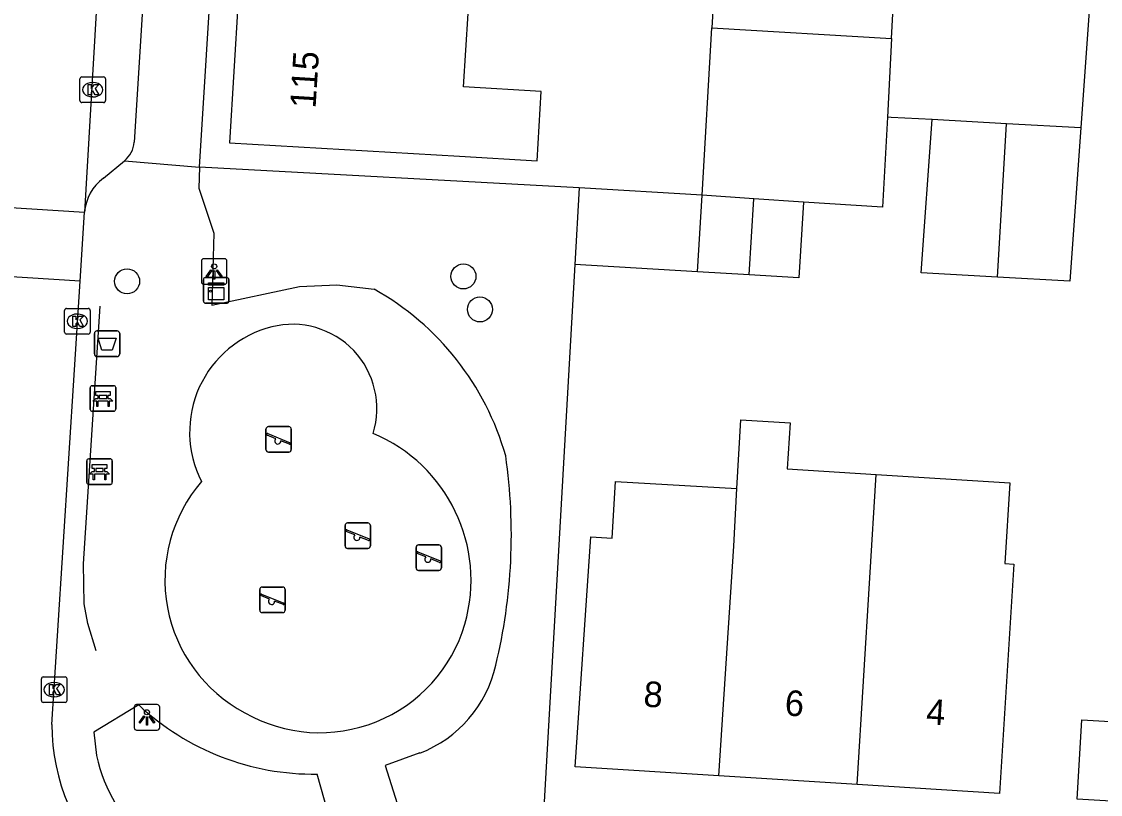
# Model space of a CAD drawing. Extents: x 160107 to 160928, y 382056 to 382918.
# Drawn here: x 160559.79 to 160601.98, y 382517.33 to 382547.57 of the extents above; entities that cross this region are included whole.
import ezdxf

# ---------------------------------------------------------------- set-up
doc = ezdxf.new("R2010")
doc.units = 0
for name, color, linetype in [('IMGEO_Afvalbak', 7, 'Continuous'), ('IMGEO_Bank', 7, 'Continuous'), ('IMGEO_Boom', 7, 'Continuous'), ('IMGEO_Groenvoorziening', 7, 'Continuous'), ('IMGEO_Hek', 7, 'Continuous'), ('IMGEO_Kast', 7, 'Continuous'), ('IMGEO_Kolk', 7, 'Continuous'), ('IMGEO_Lichtpunt', 7, 'Continuous'), ('IMGEO_Pand', 7, 'Continuous'), ('IMGEO_Pand_nummerreeks', 7, 'Continuous'), ('IMGEO_Rijbaan_lokaal_open', 7, 'Continuous'), ('IMGEO_Speelvoorziening', 7, 'Continuous'), ('IMGEO_Voetpad_open', 7, 'Continuous')]:
    doc.layers.add(name, color=color, linetype=linetype)

msp = doc.modelspace()

# ---------------------------------------------------------------- linework, layer by layer
at = {"layer": 'IMGEO_Afvalbak'}
for p, q in [((160562.74, 382535.464), (160563.53, 382535.464)), ((160563.53, 382535.464), (160562.74, 382535.464)), ((160562.64, 382534.564), (160562.64, 382535.364)), ((160562.64, 382535.364), (160562.64, 382534.564)), ((160563.63, 382535.364), (160563.63, 382534.564)), ((160563.63, 382534.564), (160563.63, 382535.364)), ((160563.53, 382534.464), (160562.74, 382534.464)), ((160562.74, 382534.464), (160563.53, 382534.464))]:
    msp.add_line(p, q, dxfattribs=at)
msp.add_lwpolyline([(160562.783, 382535.178), (160563.487, 382535.178), (160563.338, 382534.708), (160562.932, 382534.708), (160562.783, 382535.178)], dxfattribs=at)
for centre, start, end in [((160562.74, 382535.364), 90, 180), ((160562.74, 382535.364), 90, 180), ((160563.53, 382535.364), 0, 90), ((160563.53, 382535.364), 360, 90), ((160562.74, 382534.564), 180, 270), ((160562.74, 382534.564), 180, 270), ((160563.53, 382534.564), 270, 0), ((160563.53, 382534.564), 270, 0)]:
    msp.add_arc(centre, 0.1, start, end, dxfattribs=at)
at = {"layer": 'IMGEO_Bank'}
for p, q in [((160562.476, 382532.397), (160562.476, 382533.238)), ((160562.476, 382533.238), (160562.476, 382532.397)), ((160562.551, 382533.322), (160563.392, 382533.322)), ((160563.392, 382533.322), (160562.551, 382533.322)), ((160562.785, 382532.828), (160562.785, 382532.934)), ((160562.829, 382532.934), (160562.829, 382532.828)), ((160563.117, 382532.94), (160562.835, 382532.94)), ((160563.123, 382532.828), (160563.123, 382532.934)), ((160563.167, 382532.934), (160563.167, 382532.828)), ((160563.476, 382533.247), (160563.476, 382532.406)), ((160563.476, 382532.406), (160563.476, 382533.247)), ((160563.173, 382532.72), (160562.78, 382532.72)), ((160562.835, 382532.822), (160563.117, 382532.822)), ((160563.401, 382532.322), (160562.56, 382532.322)), ((160562.56, 382532.322), (160563.401, 382532.322)), ((160562.417, 382530.462), (160563.258, 382530.462)), ((160563.258, 382530.462), (160562.417, 382530.462)), ((160562.342, 382529.537), (160562.342, 382530.378)), ((160562.342, 382530.378), (160562.342, 382529.537)), ((160562.651, 382529.968), (160562.651, 382530.074)), ((160562.695, 382530.074), (160562.695, 382529.968)), ((160562.983, 382530.08), (160562.701, 382530.08)), ((160562.989, 382529.968), (160562.989, 382530.074)), ((160563.033, 382530.074), (160563.033, 382529.968)), ((160563.342, 382530.387), (160563.342, 382529.546)), ((160563.342, 382529.546), (160563.342, 382530.387)), ((160563.039, 382529.86), (160562.646, 382529.86)), ((160562.701, 382529.962), (160562.983, 382529.962)), ((160563.267, 382529.462), (160562.426, 382529.462)), ((160562.426, 382529.462), (160563.267, 382529.462))]:
    msp.add_line(p, q, dxfattribs=at)
for points in [[(160562.779, 382532.94), (160562.693, 382532.94), (160562.693, 382533.101), (160563.256, 382533.101), (160563.256, 382532.94), (160563.173, 382532.94)], [(160562.723, 382532.72), (160562.581, 382532.72), (160562.693, 382532.822), (160562.779, 382532.822)], [(160562.773, 382532.713), (160562.773, 382532.506), (160562.73, 382532.506), (160562.73, 382532.713)], [(160563.173, 382532.822), (160563.256, 382532.822), (160563.368, 382532.72), (160563.229, 382532.72)], [(160563.223, 382532.713), (160563.223, 382532.506), (160563.179, 382532.506), (160563.179, 382532.713)], [(160562.645, 382530.08), (160562.559, 382530.08), (160562.559, 382530.241), (160563.122, 382530.241), (160563.122, 382530.08), (160563.039, 382530.08)], [(160562.589, 382529.86), (160562.447, 382529.86), (160562.559, 382529.962), (160562.645, 382529.962)], [(160562.639, 382529.853), (160562.639, 382529.646), (160562.596, 382529.646), (160562.596, 382529.853)], [(160563.039, 382529.962), (160563.122, 382529.962), (160563.234, 382529.86), (160563.095, 382529.86)], [(160563.089, 382529.853), (160563.089, 382529.646), (160563.045, 382529.646), (160563.045, 382529.853)]]:
    msp.add_lwpolyline(points, dxfattribs=at)
for centre, radius, start, end in [((160562.554, 382533.244), 0.0779, 92.4484, 184.2845), ((160562.554, 382533.244), 0.0779, 92.4484, 184.2845), ((160562.778, 382532.933), 0.00671, 2.8957, 87.1043), ((160562.835, 382532.933), 0.00671, 92.8957, 177.1043), ((160563.117, 382532.933), 0.00671, 2.8957, 87.1043), ((160563.174, 382532.933), 0.00671, 92.8957, 177.1043), ((160563.398, 382533.244), 0.0779, 2.4484, 94.2845), ((160563.398, 382533.244), 0.0779, 2.4484, 94.2845), ((160562.723, 382532.713), 0.00671, 2.8957, 87.1043), ((160562.78, 382532.713), 0.00671, 92.8957, 177.1043), ((160562.778, 382532.829), 0.00671, 272.8957, 357.1043), ((160562.835, 382532.829), 0.00671, 182.8957, 267.1043), ((160563.117, 382532.829), 0.00671, 272.8957, 357.1043), ((160563.174, 382532.829), 0.00671, 182.8957, 267.1043), ((160563.172, 382532.713), 0.00671, 2.8957, 87.1043), ((160563.229, 382532.713), 0.00671, 92.8957, 177.1043), ((160562.554, 382532.4), 0.0779, 182.4484, 274.2845), ((160562.554, 382532.4), 0.0779, 182.4484, 274.2845), ((160563.398, 382532.4), 0.0779, 272.4484, 4.2845), ((160563.398, 382532.4), 0.0779, 272.4484, 4.2845), ((160562.42, 382530.384), 0.0779, 92.4484, 184.2845), ((160562.42, 382530.384), 0.0779, 92.4484, 184.2845), ((160563.264, 382530.384), 0.0779, 2.4484, 94.2845), ((160563.264, 382530.384), 0.0779, 2.4484, 94.2845), ((160562.644, 382530.073), 0.00671, 2.8957, 87.1043), ((160562.644, 382529.969), 0.00671, 272.8957, 357.1043), ((160562.701, 382530.073), 0.00671, 92.8957, 177.1043), ((160562.701, 382529.969), 0.00671, 182.8957, 267.1043), ((160562.983, 382530.073), 0.00671, 2.8957, 87.1043), ((160562.983, 382529.969), 0.00671, 272.8957, 357.1043), ((160563.04, 382530.073), 0.00671, 92.8957, 177.1043), ((160563.04, 382529.969), 0.00671, 182.8957, 267.1043), ((160562.589, 382529.853), 0.00671, 2.8957, 87.1043), ((160562.646, 382529.853), 0.00671, 92.8957, 177.1043), ((160563.038, 382529.853), 0.00671, 2.8957, 87.1043), ((160563.095, 382529.853), 0.00671, 92.8957, 177.1043), ((160563.264, 382529.54), 0.0779, 272.4484, 4.2845), ((160563.264, 382529.54), 0.0779, 272.4484, 4.2845), ((160562.42, 382529.54), 0.0779, 182.4484, 274.2845), ((160562.42, 382529.54), 0.0779, 182.4484, 274.2845)]:
    msp.add_arc(centre, radius, start, end, dxfattribs=at)
at = {"layer": 'IMGEO_Boom'}
for centre in [(160577.073, 382537.598), (160563.92, 382537.407), (160577.718, 382536.307)]:
    msp.add_circle(centre, 0.489, dxfattribs=at)
at = {"layer": 'IMGEO_Groenvoorziening'}
for points in [[(160581.6, 382541.063), (160566.75, 382541.876)], [(160581.423, 382538.059), (160580.178, 382516.126)]]:
    msp.add_lwpolyline(points, dxfattribs=at)
at = {"layer": 'IMGEO_Hek'}
msp.add_lwpolyline([(160562.715, 382522.952), (160562.379, 382524.021), (160562.241, 382524.794), (160562.21, 382526.361), (160562.864, 382536.433)], dxfattribs=at)
at = {"layer": 'IMGEO_Kast'}
for p, q in [((160566.902, 382536.629), (160566.902, 382537.47)), ((160566.902, 382537.47), (160566.902, 382536.629)), ((160566.977, 382537.554), (160567.818, 382537.554)), ((160567.818, 382537.554), (160566.977, 382537.554)), ((160567.902, 382537.479), (160567.902, 382536.638)), ((160567.902, 382536.638), (160567.902, 382537.479)), ((160567.827, 382536.554), (160566.986, 382536.554)), ((160566.986, 382536.554), (160567.827, 382536.554))]:
    msp.add_line(p, q, dxfattribs=at)
for points in [[(160567.097, 382537.344), (160567.697, 382537.344), (160567.697, 382537.259), (160567.097, 382537.259), (160567.097, 382537.344)], [(160567.097, 382537.169), (160567.697, 382537.169), (160567.697, 382536.68), (160567.097, 382536.68), (160567.097, 382537.169)]]:
    msp.add_lwpolyline(points, dxfattribs=at)
msp.add_circle((160567.181, 382537.018), 0.0377, dxfattribs=at)
for centre, start, end in [((160566.98, 382537.476), 92.4484, 184.2845), ((160566.98, 382537.476), 92.4484, 184.2845), ((160567.824, 382537.476), 2.4484, 94.2845), ((160567.824, 382537.476), 2.4484, 94.2845), ((160566.98, 382536.632), 182.4484, 274.2845), ((160566.98, 382536.632), 182.4484, 274.2845), ((160567.824, 382536.632), 272.4484, 4.2845), ((160567.824, 382536.632), 272.4484, 4.2845)]:
    msp.add_arc(centre, 0.0779, start, end, dxfattribs=at)
at = {"layer": 'IMGEO_Kolk'}
for p, q in [((160562.074, 382544.475), (160562.074, 382545.327)), ((160562.149, 382545.401), (160563.001, 382545.401)), ((160562.562, 382545.181), (160562.587, 382545.181)), ((160563.075, 382545.327), (160563.075, 382544.475)), ((160563.001, 382544.401), (160562.149, 382544.401)), ((160562.585, 382544.621), (160562.56, 382544.621)), ((160561.55, 382536.346), (160562.402, 382536.346)), ((160561.475, 382535.42), (160561.475, 382536.272)), ((160561.963, 382536.126), (160561.988, 382536.126)), ((160562.476, 382536.272), (160562.476, 382535.42)), ((160561.986, 382535.566), (160561.961, 382535.566)), ((160562.402, 382535.346), (160561.55, 382535.346)), ((160560.568, 382521.007), (160560.568, 382521.859)), ((160560.643, 382521.933), (160561.495, 382521.933)), ((160561.056, 382521.713), (160561.081, 382521.713)), ((160561.569, 382521.859), (160561.569, 382521.007)), ((160561.079, 382521.153), (160561.054, 382521.153)), ((160561.495, 382520.933), (160560.643, 382520.933))]:
    msp.add_line(p, q, dxfattribs=at)
for points in [[(160562.074, 382544.475), (160562.074, 382545.327)], [(160562.149, 382545.401), (160563.001, 382545.401)], [(160563.075, 382545.327), (160563.075, 382544.475)], [(160562.395, 382545.101), (160562.518, 382545.101), (160562.518, 382544.95), (160562.648, 382545.101), (160562.812, 382545.101), (160562.666, 382544.95), (160562.819, 382544.701), (160562.667, 382544.701), (160562.582, 382544.865), (160562.518, 382544.798), (160562.518, 382544.701), (160562.395, 382544.701), (160562.395, 382545.101)], [(160563.001, 382544.401), (160562.149, 382544.401)], [(160561.55, 382536.346), (160562.402, 382536.346)], [(160561.475, 382535.42), (160561.475, 382536.272)], [(160561.796, 382536.046), (160561.919, 382536.046), (160561.919, 382535.895), (160562.049, 382536.046), (160562.213, 382536.046), (160562.067, 382535.895), (160562.22, 382535.646), (160562.068, 382535.646), (160561.983, 382535.81), (160561.919, 382535.743), (160561.919, 382535.646), (160561.796, 382535.646), (160561.796, 382536.046)], [(160562.476, 382536.272), (160562.476, 382535.42)], [(160562.402, 382535.346), (160561.55, 382535.346)], [(160560.568, 382521.007), (160560.568, 382521.859)], [(160560.643, 382521.933), (160561.495, 382521.933)], [(160560.889, 382521.633), (160561.012, 382521.633), (160561.012, 382521.482), (160561.142, 382521.633), (160561.306, 382521.633), (160561.16, 382521.482), (160561.313, 382521.233), (160561.161, 382521.233), (160561.076, 382521.397), (160561.012, 382521.33), (160561.012, 382521.233), (160560.889, 382521.233), (160560.889, 382521.633)], [(160561.569, 382521.859), (160561.569, 382521.007)], [(160561.495, 382520.933), (160560.643, 382520.933)]]:
    msp.add_lwpolyline(points, dxfattribs=at)
for centre, start, end in [((160562.151, 382545.325), 91.552, 178.448), ((160562.151, 382545.325), 91.552, 178.448), ((160562.999, 382545.325), 1.552, 88.448), ((160562.999, 382545.325), 1.552, 88.448), ((160562.151, 382544.477), 181.552, 268.448), ((160562.151, 382544.477), 181.552, 268.448), ((160562.999, 382544.477), 271.552, 358.448), ((160562.999, 382544.477), 271.552, 358.448), ((160561.552, 382536.27), 91.552, 178.448), ((160561.552, 382536.27), 91.552, 178.448), ((160562.4, 382536.27), 1.552, 88.448), ((160562.4, 382536.27), 1.552, 88.448), ((160561.552, 382535.422), 181.552, 268.448), ((160561.552, 382535.422), 181.552, 268.448), ((160562.4, 382535.422), 271.552, 358.448), ((160562.4, 382535.422), 271.552, 358.448), ((160560.645, 382521.857), 91.552, 178.448), ((160560.645, 382521.857), 91.552, 178.448), ((160561.493, 382521.857), 1.552, 88.448), ((160561.493, 382521.857), 1.552, 88.448), ((160560.645, 382521.009), 181.552, 268.448), ((160560.645, 382521.009), 181.552, 268.448), ((160561.493, 382521.009), 271.552, 358.448), ((160561.493, 382521.009), 271.552, 358.448)]:
    msp.add_arc(centre, 0.0765, start, end, dxfattribs=at)
for centre, major_axis, ratio, start_param, end_param in [((160562.561, 382544.901), (-0.387, 0.002), 0.722429, 4.712389, 7.853982), ((160562.586, 382544.901), (-0.39, 0.002), 0.717154, 1.570796, 4.712389), ((160561.962, 382535.846), (-0.387, 0.002), 0.722429, 4.712389, 7.853982), ((160561.987, 382535.846), (-0.39, 0.002), 0.717154, 1.570796, 4.712389), ((160561.055, 382521.433), (-0.387, 0.002), 0.722429, 4.712389, 7.853982), ((160561.08, 382521.433), (-0.39, 0.002), 0.717154, 1.570796, 4.712389)]:
    msp.add_ellipse(centre, major_axis=major_axis, ratio=ratio, start_param=start_param, end_param=end_param, dxfattribs=at)
at = {"layer": 'IMGEO_Lichtpunt'}
for p, q in [((160566.824, 382538.195), (160566.824, 382537.388)), ((160566.824, 382538.195), (160566.824, 382537.388)), ((160567.726, 382538.29), (160566.918, 382538.29)), ((160567.726, 382538.29), (160566.918, 382538.29)), ((160567.82, 382537.388), (160567.82, 382538.195)), ((160567.82, 382537.388), (160567.82, 382538.195)), ((160566.918, 382537.294), (160567.726, 382537.294)), ((160566.918, 382537.294), (160567.726, 382537.294)), ((160564.198, 382520.751), (160564.198, 382519.944)), ((160564.198, 382520.751), (160564.198, 382519.944)), ((160565.1, 382520.846), (160564.292, 382520.846)), ((160565.1, 382520.846), (160564.292, 382520.846)), ((160565.194, 382519.944), (160565.194, 382520.751)), ((160565.194, 382519.944), (160565.194, 382520.751)), ((160564.292, 382519.85), (160565.1, 382519.85)), ((160564.292, 382519.85), (160565.1, 382519.85))]:
    msp.add_line(p, q, dxfattribs=at)
for points in [[(160567.198, 382537.859), (160567.237, 382537.831), (160567.049, 382537.569), (160567.011, 382537.596), (160567.198, 382537.859)], [(160567.3, 382537.811), (160567.347, 382537.811), (160567.347, 382537.489), (160567.3, 382537.489), (160567.3, 382537.811)], [(160567.41, 382537.831), (160567.448, 382537.858), (160567.635, 382537.596), (160567.596, 382537.568), (160567.41, 382537.831)], [(160564.572, 382520.415), (160564.611, 382520.387), (160564.423, 382520.125), (160564.385, 382520.152), (160564.572, 382520.415)], [(160564.674, 382520.367), (160564.721, 382520.367), (160564.721, 382520.045), (160564.674, 382520.045), (160564.674, 382520.367)], [(160564.784, 382520.387), (160564.822, 382520.414), (160565.009, 382520.152), (160564.97, 382520.124), (160564.784, 382520.387)]]:
    msp.add_lwpolyline(points, dxfattribs=at)
for centre in [(160567.323, 382537.993), (160564.697, 382520.549)]:
    msp.add_circle(centre, 0.0994, dxfattribs=at)
for centre, start, end in [((160566.918, 382538.195), 90, 180), ((160566.918, 382538.195), 90, 180), ((160567.726, 382538.195), 0, 90), ((160567.726, 382538.195), 0, 90), ((160566.918, 382537.388), 180, 270), ((160566.918, 382537.388), 180, 270), ((160567.726, 382537.388), 270, 0), ((160567.726, 382537.388), 270, 360), ((160564.292, 382520.751), 90, 180), ((160564.292, 382520.751), 90, 180), ((160565.1, 382520.751), 0, 90), ((160565.1, 382520.751), 0, 90), ((160564.292, 382519.944), 180, 270), ((160564.292, 382519.944), 180, 270), ((160565.1, 382519.944), 270, 0), ((160565.1, 382519.944), 270, 360)]:
    msp.add_arc(centre, 0.0946, start, end, dxfattribs=at)
at = {"layer": 'IMGEO_Pand'}
for points in [[(160592.846, 382552.361), (160587.104, 382552.661), (160586.789, 382547.327)], [(160593.811, 382546.912), (160593.988, 382550.289), (160595.736, 382550.197), (160595.836, 382552.098)], [(160568.265, 382548.421), (160567.919, 382542.831), (160576.915, 382542.301), (160579.95, 382542.122), (160580.11, 382544.837), (160577.08, 382545.016), (160577.255, 382547.89)], [(160586.402, 382540.78), (160586.789, 382547.327)], [(160586.789, 382547.327), (160593.811, 382546.912)], [(160593.811, 382546.912), (160593.649, 382543.828)], [(160593.649, 382543.828), (160593.464, 382540.314), (160590.37, 382540.5)], [(160597.958, 382537.57), (160594.967, 382537.733), (160595.396, 382543.732)], [(160598.31, 382543.573), (160595.396, 382543.732)], [(160597.958, 382537.57), (160598.31, 382543.573)], [(160601.217, 382543.414), (160598.31, 382543.573)], [(160601.217, 382543.414), (160600.788, 382537.415), (160597.958, 382537.57)], [(160581.6, 382541.063), (160581.423, 382538.059)], [(160586.402, 382540.78), (160581.6, 382541.063)], [(160586.219, 382537.776), (160586.402, 382540.78)], [(160588.422, 382540.637), (160586.402, 382540.78)], [(160588.243, 382537.657), (160588.422, 382540.637)], [(160590.37, 382540.5), (160588.422, 382540.637)], [(160590.37, 382540.5), (160590.193, 382537.542), (160588.243, 382537.657)], [(160586.219, 382537.776), (160581.423, 382538.059)], [(160588.243, 382537.657), (160586.219, 382537.776)], [(160587.768, 382529.308), (160587.921, 382531.994), (160589.846, 382531.872), (160589.732, 382530.075), (160593.212, 382529.855)], [(160587.053, 382518.062), (160581.442, 382518.413), (160582.049, 382527.409), (160582.89, 382527.355), (160583.016, 382529.578), (160587.768, 382529.308)], [(160593.212, 382529.855), (160598.438, 382529.525), (160598.239, 382526.369), (160598.596, 382526.346), (160598.03, 382517.375), (160592.464, 382517.723)], [(160592.464, 382517.723), (160593.212, 382529.855)], [(160587.053, 382518.062), (160587.64, 382527.05), (160587.768, 382529.308)], [(160603.248, 382520.134), (160603.071, 382517.029), (160601.074, 382517.143), (160601.251, 382520.248), (160603.248, 382520.134)], [(160592.464, 382517.723), (160587.053, 382518.062)]]:
    msp.add_lwpolyline(points, dxfattribs=at)
at = {"layer": 'IMGEO_Rijbaan_lokaal_open'}
for points in [[(160564.68, 382581.638), (160562.258, 382540.108)], [(160608.896, 382567.979), (160609.184, 382567.776), (160601.851, 382557.181), (160601.576, 382553.34), (160601.925, 382553.315), (160601.217, 382543.414)], [(160595.396, 382543.732), (160593.799, 382543.82), (160593.649, 382543.828)], [(160556.271, 382540.489), (160562.258, 382540.108)], [(160562.086, 382537.415), (160562.258, 382540.108)], [(160562.086, 382537.415), (160556.099, 382537.796)], [(160560.981, 382520.071), (160562.086, 382537.415)]]:
    msp.add_lwpolyline(points, dxfattribs=at)
msp.add_arc((160568.877, 382520.04), 7.896, 179.7755, 226.8412, dxfattribs=at)
at = {"layer": 'IMGEO_Speelvoorziening'}
for p, q in [((160569.449, 382531.723), (160570.239, 382531.723)), ((160570.239, 382531.723), (160569.449, 382531.723)), ((160569.349, 382530.823), (160569.349, 382531.623)), ((160569.349, 382531.623), (160569.349, 382530.823)), ((160569.732, 382531.251), (160569.393, 382531.388)), ((160569.418, 382531.448), (160570.294, 382531.095)), ((160570.339, 382531.623), (160570.339, 382530.823)), ((160570.339, 382530.823), (160570.339, 382531.623)), ((160570.27, 382531.035), (160569.93, 382531.172)), ((160570.239, 382530.723), (160569.449, 382530.723)), ((160569.449, 382530.723), (160570.239, 382530.723)), ((160572.542, 382527.955), (160573.332, 382527.955)), ((160573.332, 382527.955), (160572.542, 382527.955)), ((160572.442, 382527.055), (160572.442, 382527.855)), ((160572.442, 382527.855), (160572.442, 382527.055)), ((160572.825, 382527.483), (160572.486, 382527.62)), ((160572.511, 382527.68), (160573.387, 382527.327)), ((160573.432, 382527.855), (160573.432, 382527.055)), ((160573.432, 382527.055), (160573.432, 382527.855)), ((160573.363, 382527.267), (160573.023, 382527.404)), ((160575.32, 382527.097), (160576.11, 382527.097)), ((160576.11, 382527.097), (160575.32, 382527.097)), ((160573.332, 382526.955), (160572.542, 382526.955)), ((160572.542, 382526.955), (160573.332, 382526.955)), ((160575.22, 382526.197), (160575.22, 382526.997)), ((160575.22, 382526.997), (160575.22, 382526.197)), ((160575.603, 382526.625), (160575.264, 382526.762)), ((160575.289, 382526.822), (160576.165, 382526.469)), ((160576.21, 382526.997), (160576.21, 382526.197)), ((160576.21, 382526.197), (160576.21, 382526.997)), ((160576.141, 382526.409), (160575.801, 382526.546)), ((160576.11, 382526.097), (160575.32, 382526.097)), ((160575.32, 382526.097), (160576.11, 382526.097)), ((160569.108, 382524.546), (160569.108, 382525.346)), ((160569.108, 382525.346), (160569.108, 382524.546)), ((160569.208, 382525.446), (160569.998, 382525.446)), ((160569.998, 382525.446), (160569.208, 382525.446)), ((160570.098, 382525.346), (160570.098, 382524.546)), ((160570.098, 382524.546), (160570.098, 382525.346)), ((160569.491, 382524.974), (160569.152, 382525.111)), ((160569.177, 382525.171), (160570.053, 382524.818)), ((160570.029, 382524.758), (160569.689, 382524.895)), ((160569.998, 382524.446), (160569.208, 382524.446)), ((160569.208, 382524.446), (160569.998, 382524.446))]:
    msp.add_line(p, q, dxfattribs=at)
for centre, radius, start, end in [((160569.449, 382531.623), 0.1, 90, 180), ((160569.449, 382531.623), 0.1, 90, 180), ((160570.239, 382531.623), 0.1, 0, 90), ((160570.239, 382531.623), 0.1, 360, 90), ((160569.406, 382531.418), 0.0327, 68.078, 248.078), ((160569.811, 382531.161), 0.12, 130.9928, 5.1632), ((160569.449, 382530.823), 0.1, 180, 270), ((160569.449, 382530.823), 0.1, 180, 270), ((160570.239, 382530.823), 0.1, 270, 0), ((160570.239, 382530.823), 0.1, 270, 0), ((160570.282, 382531.065), 0.0327, 248.078, 68.078), ((160572.542, 382527.855), 0.1, 90, 180), ((160572.542, 382527.855), 0.1, 90, 180), ((160573.332, 382527.855), 0.1, 0, 90), ((160573.332, 382527.855), 0.1, 360, 90), ((160572.499, 382527.65), 0.0327, 68.078, 248.078), ((160572.904, 382527.393), 0.12, 130.9928, 5.1632), ((160572.542, 382527.055), 0.1, 180, 270), ((160572.542, 382527.055), 0.1, 180, 270), ((160573.332, 382527.055), 0.1, 270, 0), ((160573.332, 382527.055), 0.1, 270, 0), ((160573.375, 382527.297), 0.0327, 248.078, 68.078), ((160575.32, 382526.997), 0.1, 90, 180), ((160575.32, 382526.997), 0.1, 90, 180), ((160576.11, 382526.997), 0.1, 0, 90), ((160576.11, 382526.997), 0.1, 360, 90), ((160575.277, 382526.792), 0.0327, 68.078, 248.078), ((160575.682, 382526.535), 0.12, 130.9928, 5.1632), ((160575.32, 382526.197), 0.1, 180, 270), ((160575.32, 382526.197), 0.1, 180, 270), ((160576.11, 382526.197), 0.1, 270, 0), ((160576.11, 382526.197), 0.1, 270, 0), ((160576.153, 382526.439), 0.0327, 248.078, 68.078), ((160569.208, 382525.346), 0.1, 90, 180), ((160569.208, 382525.346), 0.1, 90, 180), ((160569.998, 382525.346), 0.1, 0, 90), ((160569.998, 382525.346), 0.1, 360, 90), ((160569.165, 382525.141), 0.0327, 68.078, 248.078), ((160569.57, 382524.884), 0.12, 130.9928, 5.1632), ((160569.208, 382524.546), 0.1, 180, 270), ((160569.208, 382524.546), 0.1, 180, 270), ((160569.998, 382524.546), 0.1, 270, 0), ((160569.998, 382524.546), 0.1, 270, 0), ((160570.041, 382524.788), 0.0327, 248.078, 68.078)]:
    msp.add_arc(centre, radius, start, end, dxfattribs=at)
at = {"layer": 'IMGEO_Voetpad_open'}
for points in [[(160566.75, 382541.876), (160569.255, 382582.058)], [(160566.451, 382578.939), (160564.192, 382542.847)], [(160562.995, 382541.44), (160563.817, 382542.125)], [(160563.817, 382542.125), (160566.75, 382541.876)], [(160566.75, 382541.876), (160566.721, 382541.052), (160567.317, 382539.292), (160567.237, 382536.479), (160570.662, 382537.201), (160572.125, 382537.267), (160573.58, 382537.097)], [(160564.375, 382520.836), (160562.621, 382519.768), (160562.725, 382518.851)], [(160575.371, 382518.955), (160574.005, 382518.469), (160574.643, 382516.487), (160579.471, 382516.183)], [(160568.361, 382513.894), (160572.643, 382513.553), (160571.355, 382518.128)]]:
    msp.add_lwpolyline(points, dxfattribs=at)
for centre, radius, start, end in [((160563.192, 382542.908), 1.002, 308.5907, 356.5154), ((160564.046, 382539.988), 1.792, 125.916, 176.1722), ((160568.28, 382527.626), 10.853, 15.7671, 60.7705), ((160570.603, 382531.51), 4.239, 104.0167, 207.1297), ((160570.388, 382532.426), 3.299, 342.8102, 104.2464), ((160571.154, 382525.712), 6.215, 343.9695, 67.4324), ((160557.22, 382527.49), 21.725, 346.4218, 8.1648), ((160571.29, 382525.728), 5.891, 139.2073, 241.9525), ((160571.455, 382525.66), 5.911, 240.2342, 343.6461), ((160573.632, 382523.456), 4.826, 291.1234, 347.2222), ((160571.223, 382528.138), 10.01, 226.8356, 270.7553), ((160568.914, 382520.205), 6.336, 192.3436, 264.9916)]:
    msp.add_arc(centre, radius, start, end, dxfattribs=at)

# ---------------------------------------------------------------- texts
at = {"layer": 'IMGEO_Pand_nummerreeks'}
for s, rotation, p in [('115', 86.4615, (160571.288, 382544.155)), ('8', 356.4194, (160584.093, 382520.772)), ('6', 356.4194, (160589.618, 382520.426)), ('4', 356.4194, (160595.147, 382520.08))]:
    msp.add_text(s, height=1, rotation=rotation, dxfattribs=at).set_placement(p)

doc.saveas('drawing.dxf')
